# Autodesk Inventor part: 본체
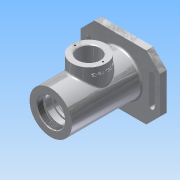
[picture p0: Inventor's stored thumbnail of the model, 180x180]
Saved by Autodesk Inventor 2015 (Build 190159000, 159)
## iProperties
Created: 2017-10
Part Number: 본체
Material: 알루미늄 6061
Document SubType Name: Modeling
Designer: Administrator
Density: 2.7 g/cm^3
Appearance: 알루미늄 - 평지
Author: Administrator
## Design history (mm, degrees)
sketch "스케치1"
  geometry: C1 r 31 at (0, 0); 1 further point
  constraints: 1 centre point, 1 coincident
  dimensions: "d0" = 62 diameter of C1
extrude "돌출1" new body sketch "스케치1" distance "d1" = 102; taper "d2" = 0 deg
sketch "스케치2"
  geometry: L1 (-58, 47)-(58, 47); L2 (58, 47)-(58, -47); L3 (58, -47)-(-58, -47); L4 (-58, -47)-(-58, 47); C1 r 31 at (0, 0) reference; 2 further points
  constraints: 8 end point, 2 midpoint, 2 parallel, 1 horizontal, 1 horizontal alignment, 1 perpendicular, 1 vertical alignment
  dimensions: "d3" = 94 distance of L1.end L2.end; "d4" = 116 distance of L2.end L3.end
extrude "돌출2" join sketch "스케치2" distance "d5" = 10; taper "d6" = 0 deg
sketch "스케치3"
  geometry: C1 r 35 at (0, 0); 1 further point
  constraints: 1 centre point, 1 coincident
  dimensions: "d7" = 70 diameter of C1
extrude "돌출3" join sketch "스케치3" distance "d8" = 3; taper "d9" = 0 deg
chamfer "모따기1" distance "d10" = 20; stored, may be unused: second distance "d11" = 2, angle "d12" = 45 deg
sketch "스케치4"
  geometry: L1 (-46, 20)-(-46, -20); L2 (-42, 20)-(-42, -20); L3 (-50, -20)-(-50, 20); C1 r 35 at (0, 0) reference; A1 r 4 centre (-46, 20) between (-42, 20) and (-50, 20); A2 r 4 centre (-46, -20) between (-50, -20) and (-42, -20); 1 further point
  constraints: 8 end point, 4 point on circle, 4 tangent, 2 centre point, 1 midpoint, 1 parallel, 1 vertical
  dimensions: "d13" = 40 distance of L1.start L1.end; "d14" = 20 vertical distance of L1.end C1.centre; "d15" = 46 distance from line of C1.centre L1; "d16" = 4 radius of A1
extrude "돌출4" cut sketch "스케치4" stored distance "d17" = 3; taper "d18" = 0 deg
node "작업 평면1"
sketch "스케치5"
  geometry: L1 (-31, -102)-(31, -102) reference; L2 (-31, 0)-(31, 0) reference; C1 r 25 at (0, -56); 2 further points
  constraints: 1 centre point, 1 midpoint, 1 vertical alignment
  dimensions: "d20" = 50 diameter of C1; "d21" = 56 distance from line of L2 C1.centre
extrude "돌출5" join sketch "스케치5" stored distance "d22" = 3; taper "d23" = 0 deg
sketch "스케치6"
  geometry: C1 r 31 at (0, 0) reference; 1 further point
  constraints: 1 coincident
hole "구멍1" sketch "스케치6" at (0, 0) diameter "d24" = 40.376; stored, may be unused: countersink angle "d28" = 90 deg, drill point angle "d30" = 118 deg; dims "d25" = 9, "d26" = 4, "d27" = 2, "d29" = 9
sketch "스케치7"
  geometry: L1 (35, -112)-(35, -115) reference; L2 (35, -115)-(-35, -115) reference; L3 (-35, -115)-(-35, -112) reference; L4 (-35, -112)-(-47, -112) reference; L5 (-47, -112)-(-47, -102) reference; L6 (-47, -102)-(-31, -102) reference; L7 (-31, -102)-(-31, 0) reference; L8 (-31, 0)-(-20.188, 0) reference; L9 (-20.188, 0)-(-20.188, -9) reference; L10 (-20.188, -9)-(0, -21.13) reference; L11 (0, -21.13)-(20.188, -9) reference; L12 (20.188, -9)-(20.188, 0) reference; L13 (20.188, 0)-(31, 0) reference; L14 (31, 0)-(31, -31) reference; L15 (31, -31)-(47, -31) reference; L16 (47, -31)-(47, -81) reference; L17 (47, -81)-(31, -81) reference; L18 (31, -81)-(31, -102) reference; L19 (31, -102)-(47, -102) reference; L20 (47, -102)-(47, -112) reference; L21 (47, -112)-(35, -112) reference; L22 (0, 45)-(0, -188); L23 (0, -9)-(24, -9); L24 (24, -9)-(24, -12); L25 (24, -12)-(20, -12); L26 (20, -12)-(20, -21); L27 (20, -21)-(17.5, -21); L28 (17.5, -21)-(17.5, -24.25); L29 (17.5, -24.25)-(18.5, -24.25); L30 (18.5, -24.25)-(18.5, -26); L31 (18.5, -26)-(17.5, -26); L32 (17.5, -26)-(17.5, -37); L33 (17.5, -37)-(26, -37); L34 (26, -37)-(26, -75); L35 (26, -75)-(17.5, -75); L36 (17.5, -75)-(17.5, -86); L37 (17.5, -86)-(16.5, -86); L38 (16.5, -86)-(16.5, -91); L39 (16.5, -91)-(10, -91); L40 (10, -91)-(10, -93.7); L41 (10, -93.7)-(12.5, -93.7); L42 (12.5, -93.7)-(12.5, -100.3); L43 (12.5, -100.3)-(12.904, -101); L44 (12.904, -101)-(16, -101); L45 (16, -101)-(22, -115); L46 (22, -115)-(0, -115); L47 (0, -115)-(0, -9); 1 further point
  constraints: 52 end point, 10 horizontal, 8 vertical, 7 point on line, 4 perpendicular, 1 collinear, 1 midpoint
  dimensions: "d31" = 48 diameter of L23.end L22; "d32" = 3 distance of L23.end L24.end; "d33" = 40 diameter of L26 L22; "d34" = 21 distance from line of L26.end L13; "d35" = 35 diameter of L28 L22; "d36" = 37 diameter of L30 L22; "d37" = 1.75 distance of L29.end L30.end; "d39" = 26 distance between parallel lines of L13 L31; "d40" = 11 distance of L31.end L32.end; "d41" = 52 diameter of L33.end L22; "d42" = 38 distance of L33.end L34.end; "d43" = 60 vertical distance of L30.end L36.end; "d44" = 33 diameter of L37.end L22; "d45" = 5 distance of L37.end L38.end; "d46" = 20 diameter of L39.end L22; "d47" = 2.7 distance of L39.end L40.end; "d48" = 25 diameter of L41.end L22; "d49" = 6.6 distance of L41.end L42.end; "d50" = 30 deg angle of L42 L43; "d51" = 0.7 vertical distance of L42.end L43.end; "d52" = 32 diameter of L44.end L22; "d53" = 44 diameter of L45.end L22
revolve "회전1" sketch "스케치7" stored, may be unused: angle "d54" = 90 deg
fillet "모깎기1" dims "d55" = 3
fillet "모깎기2" dims "d56" = 3
fillet "모깎기3" dims "d57" = 0.3
fillet "모깎기4" dims "d58" = 3
fillet "모깎기5" dims "d59" = 0.3
fillet "모깎기6" dims "d60" = 3
fillet "모깎기7" dims "d61" = 3
chamfer "모따기2" distance "d62" = 1; stored, may be unused: second distance "d63" = 2, angle "d64" = 45 deg
sketch "스케치8"
  geometry: C1 r 25 at (0, 0) reference; C2 r 16 at (0, 0); 1 further point
  constraints: 1 centre point, 1 coincident
  dimensions: "d65" = 32 diameter of C2
extrude "돌출6" cut sketch "스케치8" stored distance "d66" = 3; taper "d67" = 0 deg
sketch "스케치9"
  geometry: C1 r 25 at (0, 0) reference; A1 r 20.5 centre (0, 0) between (-20.5, 0) and (20.5, 0); 1 further point
  constraints: 2 point on circle, 1 centre point, 1 coincident
  dimensions: "d68" = 41 diameter of A1
hole "구멍2" sketch "스케치9" at (-20.5, 0), (20.5, 0) diameter "d69" = 2.459; stored, may be unused: countersink angle "d73" = 90 deg, drill point angle "d75" = 118 deg; dims "d70" = 6, "d71" = 4, "d72" = 2, "d74" = 8
node "작업 평면2"
sketch "스케치10"
  geometry: L1 (42, -38.5)-(42, -73.5); L2 (42, -73.5)-(32, -73.5); L3 (32, -73.5)-(32, -38.5); L4 (32, -38.5)-(42, -38.5); L5 (-31, 0)-(31, 0) reference; L6 (47, -31)-(47, -81) reference; 4 further points
  constraints: 2 midpoint, 1 horizontal alignment, 1 vertical alignment, 2 other
  dimensions: "d77" = 35 distance of L1.start L1.end; "d78" = 10 distance of L1.end L2.end; "d79" = 56 distance from line of L5 point (37, -56); "d80" = 10 distance from line of point (37, -56) L6
feature "엠보싱1" sketch "스케치10" dims "d81" = 0.5, "d82" = 0
chamfer "모따기3" distance "d83" = 1; stored, may be unused: second distance "d84" = 2, angle "d85" = 45 deg
node "솔리드1"
mirror "대칭1"
node "투영된 루프1"
node "절단 모서리 투영1"
other parameters: "d19" = 47, "d76" = 36.25
